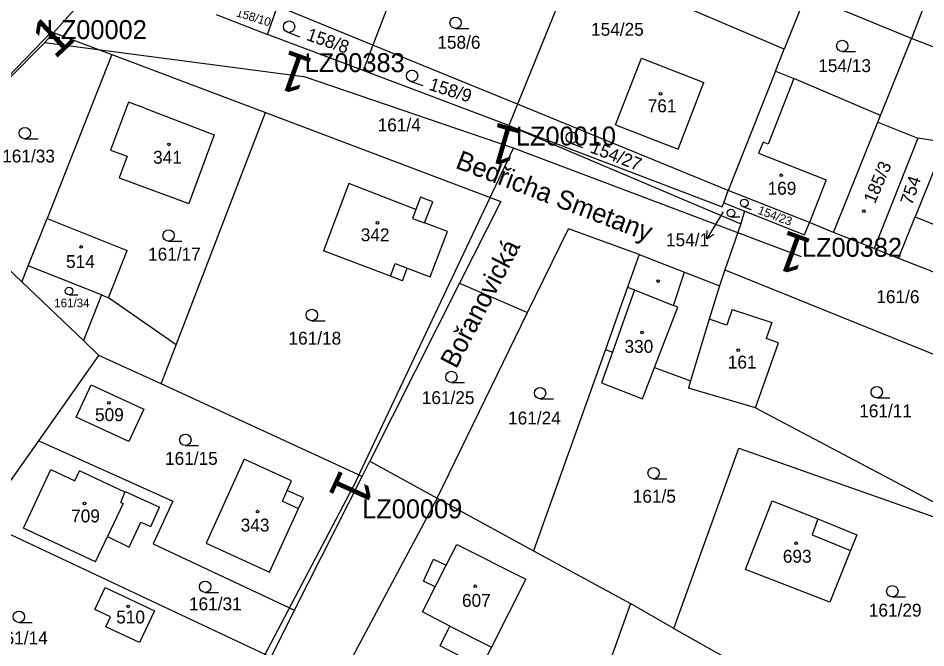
# Model space of a CAD drawing. Extents: x -738131 to -734179, y -1033447 to -1030078.
# Drawn here: x -736264.3 to -736144.6, y -1032442 to -1032359 of the extents above; entities that cross this region are included whole.
import ezdxf

# ---------------------------------------------------------------- set-up
doc = ezdxf.new("R2010")
doc.units = 0
for name, color, linetype in [('ftf_2050', 7, 'Continuous'), ('ftf_3010', 7, 'Continuous'), ('ftf_3010_ftf_3010_gtda_3015_gtda_3015_1', 7, 'Continuous'), ('ftf_nu', 7, 'Continuous'), ('Vrstva 1', 7, 'Continuous'), ('Vrstva 2', 7, 'Continuous'), ('Vrstva 3', 7, 'Continuous'), ('Vrstva 4', 7, 'Continuous'), ('Vrstva 5', 7, 'Continuous'), ('Vrstva 7', 7, 'Continuous')]:
    doc.layers.add(name, color=color, linetype=linetype)

msp = doc.modelspace()

# ---------------------------------------------------------------- linework, layer by layer
at = {"layer": 'ftf_2050'}
for points in [[(-736260.81, -1032362.16), (-736232.21, -1032330.19)], [(-736292.03, -1032393.62), (-736260.81, -1032362.16)], [(-736260.81, -1032362.16), (-736226.71, -1032366.65), (-736226.67, -1032366.68)], [(-736161.03, -1032390.44), (-736199.03, -1032376.09), (-736226.71, -1032366.65)], [(-736219.74, -1032419.93), (-736199.03, -1032376.09)], [(-736219.74, -1032419.93), (-736241.42, -1032461.24), (-736253.37, -1032482.1), (-736241.42, -1032461.24)]]:
    msp.add_lwpolyline(points, dxfattribs=at)
at = {"layer": 'Vrstva 1'}
for points in [[(-736212.82, -1032350.14), (-736217.57, -1032362.52)], [(-736190.8, -1032351.31), (-736198.5, -1032370.32)], [(-736163.32, -1032363.06), (-736190.8, -1032351.31)], [(-736143.39, -1032353.46), (-736146.54, -1032361.62)], [(-736160.47, -1032355.87), (-736163.32, -1032363.06)], [(-736146.54, -1032361.62), (-736160.47, -1032355.87)], [(-736231.46, -1032361.12), (-736230.15, -1032357.38)], [(-736217.57, -1032362.52), (-736230.15, -1032357.38)], [(-736238.22, -1032358.49), (-736231.46, -1032361.12)], [(-736278.41, -1032379.91), (-736259.94, -1032360.75)], [(-736259.94, -1032360.75), (-736252, -1032363.75)], [(-736218.85, -1032365.86), (-736231.46, -1032361.12)], [(-736150.62, -1032371.79), (-736146.54, -1032361.62)], [(-736131.88, -1032367.31), (-736146.54, -1032361.62)], [(-736217.57, -1032362.52), (-736218.85, -1032365.86)], [(-736198.5, -1032370.32), (-736217.57, -1032362.52)], [(-736252, -1032363.75), (-736260.53, -1032385.38)], [(-736252, -1032363.75), (-736231.73, -1032371.42)], [(-736164.47, -1032365.97), (-736163.32, -1032363.06)], [(-736185.58, -1032373.04), (-736182.15, -1032364.23)], [(-736182.15, -1032364.23), (-736173.9, -1032367.43)], [(-736199.63, -1032373.1), (-736218.85, -1032365.86)], [(-736164.47, -1032365.97), (-736170.7, -1032381.68)], [(-736164.47, -1032365.97), (-736162.05, -1032366.92)], [(-736177.32, -1032376.23), (-736173.9, -1032367.43)], [(-736150.62, -1032371.79), (-736162.05, -1032366.92)], [(-736249.78, -1032370.03), (-736252.17, -1032376.36)], [(-736247.62, -1032370.85), (-736249.78, -1032370.03)], [(-736247.62, -1032370.85), (-736238.49, -1032374.33)], [(-736198.5, -1032370.32), (-736199.63, -1032373.1)], [(-736170.7, -1032381.68), (-736198.5, -1032370.32)], [(-736243.49, -1032402.06), (-736231.73, -1032371.42)], [(-736231.73, -1032371.42), (-736200.7, -1032383.16)], [(-736150.99, -1032372.7), (-736150.62, -1032371.79)], [(-736199.63, -1032373.1), (-736169.05, -1032386.08)], [(-736199.63, -1032373.1), (-736171.48, -1032383.84)], [(-736185.58, -1032373.04), (-736177.32, -1032376.23)], [(-736156.82, -1032387.24), (-736150.99, -1032372.7)], [(-736150.99, -1032372.7), (-736145.68, -1032374.79)], [(-736238.49, -1032374.33), (-736241.83, -1032383.4)], [(-736145.68, -1032374.79), (-736151.46, -1032389.34)], [(-736142.11, -1032375.35), (-736146.06, -1032385.19)], [(-736142.11, -1032375.35), (-736145.68, -1032374.79)], [(-736252.17, -1032376.36), (-736249.98, -1032377.16)], [(-736249.98, -1032377.16), (-736251.03, -1032380.02)], [(-736263.86, -1032393.75), (-736278.41, -1032379.91)], [(-736251.03, -1032380.02), (-736241.83, -1032383.4)], [(-736220.71, -1032380.77), (-736224.07, -1032389.64)], [(-736211.88, -1032384.2), (-736220.71, -1032380.77)], [(-736171.29, -1032383.32), (-736170.7, -1032381.68)], [(-736159.98, -1032385.92), (-736170.7, -1032381.68)], [(-736211.27, -1032382.57), (-736211.88, -1032384.2)], [(-736209.66, -1032383.18), (-736211.27, -1032382.57)], [(-736200.7, -1032383.16), (-736206.13, -1032393.94)], [(-736210.73, -1032385.98), (-736209.66, -1032383.18)], [(-736171.48, -1032383.84), (-736171.29, -1032383.32)], [(-736171.29, -1032383.32), (-736168.49, -1032384.43)], [(-736263.03, -1032391.64), (-736260.53, -1032385.38)], [(-736260.53, -1032385.38), (-736249.95, -1032389.61)], [(-736169.05, -1032386.08), (-736168.49, -1032384.43)], [(-736168.49, -1032384.43), (-736160.63, -1032387.55)], [(-736148.26, -1032390.6), (-736146.06, -1032385.19)], [(-736207.73, -1032387.12), (-736210.73, -1032385.98)], [(-736197.16, -1032397.79), (-736191.78, -1032386.74)], [(-736182.43, -1032390.13), (-736191.78, -1032386.74)], [(-736169.05, -1032386.08), (-736171.13, -1032392.17)], [(-736160.63, -1032387.55), (-736159.98, -1032385.92)], [(-736156.82, -1032387.24), (-736159.98, -1032385.92)], [(-736210, -1032393.08), (-736207.73, -1032387.12)], [(-736151.46, -1032389.34), (-736156.82, -1032387.24)], [(-736252.42, -1032395.84), (-736249.95, -1032389.61)], [(-736215.25, -1032393), (-736224.07, -1032389.64)], [(-736182.43, -1032390.13), (-736183.97, -1032394.45)], [(-736182.43, -1032390.13), (-736176.46, -1032392.46)], [(-736151.46, -1032389.34), (-736148.26, -1032390.6)], [(-736148.26, -1032390.6), (-736128.1, -1032398.51)], [(-736263.86, -1032393.75), (-736263.03, -1032391.64)], [(-736253.35, -1032395.47), (-736263.03, -1032391.64)], [(-736213.67, -1032393.6), (-736213.03, -1032391.93)], [(-736213.03, -1032391.93), (-736210, -1032393.08)], [(-736176.46, -1032392.46), (-736171.85, -1032394.26)], [(-736171.13, -1032392.17), (-736171.85, -1032394.26)], [(-736171.13, -1032392.17), (-736131.75, -1032408.06)], [(-736263.86, -1032393.75), (-736255.73, -1032401.49)], [(-736206.13, -1032393.94), (-736217.97, -1032417.42)], [(-736213.67, -1032393.6), (-736215.25, -1032393)], [(-736206.13, -1032393.94), (-736197.16, -1032397.79)], [(-736183.97, -1032394.45), (-736186.9, -1032402.66)], [(-736171.85, -1032394.26), (-736173.2, -1032398.69)], [(-736253.35, -1032395.47), (-736255.73, -1032401.49)], [(-736243.49, -1032402.06), (-736252.42, -1032395.84)], [(-736170.17, -1032397.41), (-736170.87, -1032399.48)], [(-736170.17, -1032397.41), (-736164.97, -1032399.13)], [(-736209.07, -1032422.28), (-736197.16, -1032397.79)], [(-736173.2, -1032398.69), (-736175.66, -1032406.8)], [(-736170.87, -1032399.48), (-736173.2, -1032398.69)], [(-736164.97, -1032399.13), (-736165.68, -1032401.24)], [(-736255.73, -1032401.49), (-736253.68, -1032403.44)], [(-736245.47, -1032407.22), (-736243.49, -1032402.06)], [(-736167.11, -1032410.36), (-736164.08, -1032401.78)], [(-736164.08, -1032401.78), (-736165.68, -1032401.24)], [(-736261.63, -1032414.7), (-736253.68, -1032403.44)], [(-736245.47, -1032407.22), (-736253.68, -1032403.44)], [(-736186.9, -1032402.66), (-736196.38, -1032429.21)], [(-736185.97, -1032403.01), (-736187.41, -1032407.05)], [(-736186.9, -1032402.66), (-736185.97, -1032403.01)], [(-736182.02, -1032409.16), (-736180.42, -1032405.05)], [(-736180.42, -1032405.05), (-736175.66, -1032406.8)], [(-736187.41, -1032407.05), (-736182.02, -1032409.16)], [(-736175.66, -1032406.8), (-736175.96, -1032407.77)], [(-736256.69, -1032411.59), (-736254.73, -1032407.34)], [(-736254.73, -1032407.34), (-736247.77, -1032410.55)], [(-736218.98, -1032419.42), (-736245.47, -1032407.22)], [(-736167.11, -1032410.36), (-736175.96, -1032407.77)], [(-736247.77, -1032410.55), (-736249.73, -1032414.8)], [(-736167.11, -1032410.36), (-736137.84, -1032425.83)], [(-736249.73, -1032414.8), (-736256.69, -1032411.59)], [(-736269.14, -1032425.33), (-736261.63, -1032414.7)], [(-736261.63, -1032414.7), (-736243.95, -1032422.67)], [(-736177.86, -1032439.46), (-736169.31, -1032415.67)], [(-736169.31, -1032415.67), (-736138.11, -1032426.67)], [(-736234.53, -1032417.15), (-736235.76, -1032419.85)], [(-736228.29, -1032419.99), (-736234.53, -1032417.15)], [(-736218.98, -1032419.42), (-736217.97, -1032417.42)], [(-736217.97, -1032417.42), (-736209.07, -1032422.28)], [(-736263.63, -1032426.24), (-736260.03, -1032418.52)], [(-736260.03, -1032418.52), (-736256.86, -1032420)], [(-736256.86, -1032420), (-736256.25, -1032418.69)], [(-736250.26, -1032421.5), (-736256.25, -1032418.69)], [(-736235.76, -1032419.85), (-736239.55, -1032428.2)], [(-736228.85, -1032421.28), (-736228.29, -1032419.99)], [(-736227.88, -1032437.06), (-736218.98, -1032419.42)], [(-736250.26, -1032421.5), (-736250.21, -1032421.39)], [(-736250.21, -1032421.39), (-736245.69, -1032423.47)], [(-736226.71, -1032422.26), (-736228.85, -1032421.28)], [(-736227.35, -1032423.66), (-736226.71, -1032422.26)], [(-736209.07, -1032422.28), (-736224.81, -1032451.78)], [(-736209.07, -1032422.28), (-736196.38, -1032429.21)], [(-736168.42, -1032431.68), (-736164.89, -1032422.64)], [(-736164.89, -1032422.64), (-736158.88, -1032424.99)], [(-736246.86, -1032426.03), (-736245.69, -1032423.47)], [(-736243.95, -1032422.67), (-736246.53, -1032428.3)], [(-736231.19, -1032432.03), (-736227.35, -1032423.66)], [(-736158.88, -1032424.99), (-736153.72, -1032427.11)], [(-736269.14, -1032425.33), (-736230.99, -1032443.24)], [(-736254.12, -1032430.68), (-736263.63, -1032426.24)], [(-736249.68, -1032428.73), (-736248.15, -1032425.45)], [(-736248.15, -1032425.45), (-736246.86, -1032426.03)], [(-736254.12, -1032430.68), (-736252.56, -1032427.36)], [(-736252.56, -1032427.36), (-736249.68, -1032428.73)], [(-736153.72, -1032427.11), (-736154.56, -1032429.17)], [(-736246.53, -1032428.3), (-736227.88, -1032437.06)], [(-736239.55, -1032428.2), (-736231.19, -1032432.03)], [(-736207.9, -1032431.14), (-736206.49, -1032428.4)], [(-736206.49, -1032428.4), (-736197.39, -1032432.97)], [(-736196.38, -1032429.21), (-736183.6, -1032436.18)], [(-736154.56, -1032429.17), (-736157.31, -1032436.02)], [(-736210.87, -1032433.24), (-736209.55, -1032430.35)], [(-736209.55, -1032430.35), (-736207.9, -1032431.14)], [(-736157.31, -1032436.02), (-736168.42, -1032431.68)], [(-736209.35, -1032434), (-736210.87, -1032433.24)], [(-736197.39, -1032432.97), (-736201.92, -1032441.96)], [(-736254.22, -1032436.96), (-736252.87, -1032434.07)], [(-736252.87, -1032434.07), (-736246.35, -1032437.13)], [(-736211, -1032437.3), (-736209.35, -1032434)], [(-736252.15, -1032437.93), (-736254.22, -1032436.96)], [(-736183.6, -1032436.18), (-736192.74, -1032461.81)], [(-736177.86, -1032439.46), (-736183.6, -1032436.18)], [(-736252.76, -1032439.24), (-736252.15, -1032437.93)], [(-736246.35, -1032437.13), (-736248.32, -1032441.32)], [(-736230.99, -1032443.24), (-736227.88, -1032437.06)], [(-736207.39, -1032439.15), (-736211, -1032437.3)], [(-736248.32, -1032441.32), (-736252.76, -1032439.24)], [(-736208.69, -1032441.76), (-736207.39, -1032439.15)], [(-736177.86, -1032439.46), (-736170.55, -1032443.63)], [(-736203.28, -1032444.56), (-736208.69, -1032441.76)], [(-736201.92, -1032441.96), (-736203.28, -1032444.56)]]:
    msp.add_lwpolyline(points, dxfattribs=at)
at = {"layer": 'Vrstva 3'}
for p, q in [((-736206.65, -1032360.31), (-736204.9, -1032360.31)), ((-736228.87, -1032360.78), (-736227.24, -1032361.4)), ((-736155.66, -1032363.37), (-736153.91, -1032363.37)), ((-736212.63, -1032367.27), (-736210.98, -1032367.84)), ((-736263.46, -1032374.87), (-736261.71, -1032374.87)), ((-736191.57, -1032375.42), (-736189.93, -1032376.02)), ((-736168.77, -1032383.81), (-736167.67, -1032384.22)), ((-736170.34, -1032385.17), (-736169.17, -1032385.17)), ((-736244.5, -1032388.38), (-736242.75, -1032388.38)), ((-736257.62, -1032395.46), (-736256.45, -1032395.46)), ((-736225.61, -1032398.87), (-736223.86, -1032398.87)), ((-736207.21, -1032407.04), (-736205.46, -1032407.04)), ((-736195.51, -1032409.17), (-736193.76, -1032409.17)), ((-736151.12, -1032409.05), (-736149.37, -1032409.05)), ((-736242.29, -1032415.34), (-736240.54, -1032415.34)), ((-736180.54, -1032419.72), (-736178.79, -1032419.72)), ((-736239.68, -1032434.72), (-736237.93, -1032434.72)), ((-736149.06, -1032435.32), (-736147.31, -1032435.32)), ((-736264.24, -1032438.68), (-736262.49, -1032438.68))]:
    msp.add_line(p, q, dxfattribs=at)
for centre, radius in [((-736206.65, -1032359.56), 0.75), ((-736228.61, -1032360.08), 0.75), ((-736155.66, -1032362.62), 0.75), ((-736212.39, -1032366.56), 0.75), ((-736263.46, -1032374.12), 0.75), ((-736191.32, -1032374.72), 0.75), ((-736168.59, -1032383.34), 0.503), ((-736170.34, -1032384.67), 0.503), ((-736244.5, -1032387.63), 0.75), ((-736257.62, -1032394.96), 0.503), ((-736225.61, -1032398.12), 0.75), ((-736207.21, -1032406.29), 0.75), ((-736195.51, -1032408.42), 0.75), ((-736151.12, -1032408.3), 0.75), ((-736242.29, -1032414.59), 0.75), ((-736180.54, -1032418.97), 0.75), ((-736239.68, -1032433.97), 0.75), ((-736149.06, -1032434.57), 0.75), ((-736264.24, -1032437.93), 0.75)]:
    msp.add_circle(centre, radius, dxfattribs=at)
at = {"layer": 'Vrstva 4'}
for points in [[(-736162.05, -1032366.92), (-736165.45, -1032375.56)], [(-736166.1, -1032375.3), (-736166.69, -1032376.79)], [(-736165.45, -1032375.56), (-736166.1, -1032375.3)], [(-736166.69, -1032376.79), (-736157.77, -1032380.3)], [(-736157.77, -1032380.3), (-736159.98, -1032385.92)], [(-736211.88, -1032384.2), (-736212.33, -1032385.37)], [(-736212.33, -1032385.37), (-736210.73, -1032385.98)], [(-736146.06, -1032385.19), (-736139.95, -1032387.64)], [(-736215.25, -1032393), (-736214.61, -1032391.33)], [(-736214.61, -1032391.33), (-736213.03, -1032391.93)], [(-736177.9, -1032396.88), (-736176.46, -1032392.46)], [(-736183.04, -1032394.82), (-736185.97, -1032403.01)], [(-736183.97, -1032394.45), (-736183.04, -1032394.82)], [(-736183.04, -1032394.82), (-736177.9, -1032396.88)], [(-736253.35, -1032395.47), (-736252.42, -1032395.84)], [(-736180.42, -1032405.05), (-736177.34, -1032397.1)], [(-736177.34, -1032397.1), (-736177.9, -1032396.88)], [(-736229.49, -1032422.69), (-736228.85, -1032421.28)], [(-736250.81, -1032422.86), (-736250.26, -1032421.5)], [(-736250.51, -1032422.97), (-736252.56, -1032427.36)], [(-736250.81, -1032422.86), (-736250.51, -1032422.97)], [(-736229.49, -1032422.69), (-736227.35, -1032423.66)], [(-736158.88, -1032424.99), (-736159.64, -1032427.14)], [(-736159.64, -1032427.14), (-736154.56, -1032429.17)], [(-736209.35, -1032434), (-736207.9, -1032431.14)], [(-736207.39, -1032439.15), (-736201.92, -1032441.96)]]:
    msp.add_lwpolyline(points, dxfattribs=at)
at = {"layer": 'Vrstva 5'}
for centre in [(-736179.63, -1032368.95), (-736244.45, -1032375.61), (-736163.7, -1032379.69), (-736152.8, -1032384.43), (-736216.97, -1032385.96), (-736256.04, -1032389.14), (-736179.95, -1032393.64), (-736182.07, -1032400.42), (-736169.37, -1032402.77), (-736252.36, -1032409.71), (-736255.6, -1032422.99), (-736232.76, -1032424.06), (-736161.73, -1032428.24), (-736204.05, -1032433.91), (-736249.84, -1032436.56)]:
    msp.add_circle(centre, 0.175, dxfattribs=at)
at = {"layer": 'Vrstva 7'}
for p, q in [((-736172, -1032385.5), (-736173.54, -1032388.08)), ((-736173.54, -1032388.08), (-736173.46, -1032386.96)), ((-736173.54, -1032388.08), (-736172.6, -1032387.47))]:
    msp.add_line(p, q, dxfattribs=at)
msp.add_lwpolyline([(-736171.43, -1032384.55), (-736172, -1032385.5)], dxfattribs=at)

# ---------------------------------------------------------------- texts
at = {"layer": 'ftf_3010'}
for rotation, p in [(43.2385, (-736259.51, -1032364.5)), (160.2626, (-736225.22, -1032364.42)), (163.8283, (-736197.68, -1032373.77)), (159.9849, (-736159.48, -1032388.22)), (245.4227, (-736221.84, -1032418.26))]:
    msp.add_text('1', height=5.2, rotation=rotation, dxfattribs=at).set_placement(p)
at = {"layer": 'ftf_3010_ftf_3010_gtda_3015_gtda_3015_1'}
for s, p in [('LZ00002', (-736260.57, -1032361.72)), ('LZ00383', (-736226.56, -1032366.08)), ('LZ00382', (-736160.98, -1032390.44))]:
    msp.add_text(s, height=2.5, dxfattribs=at).set_placement(p)
for s, p in [('LZ00010', (-736198.7, -1032375.76)), ('LZ00009', (-736218.97, -1032424.94))]:
    msp.add_text(s, height=2.5, rotation=0, dxfattribs=at).set_placement(p)
at = {"layer": 'ftf_nu'}
for s, rotation, p in [('Bedřicha Smetany', 339.0302, (-736206.8, -1032378.68)), ('Bořanovická', 62.4769, (-736206.57, -1032405.32))]:
    msp.add_text(s, height=2.5, rotation=rotation, dxfattribs=at).set_placement(p)
at = {"layer": 'Vrstva 2'}
for s, height, rotation, p in [('158/10', 1.14, 342.723, (-736235.67, -1032358.69)), ('158/8', 1.7, 340.8862, (-736226.44, -1032361.81)), ('158/9', 1.7, 342.397, (-736210.28, -1032368.39)), ('154/27', 1.7, 338.8629, (-736189.03, -1032376.63)), ('185/3', 1.7, 66.8598, (-736151.36, -1032383.55)), ('754', 1.7, 71.6289, (-736146.45, -1032383.73)), ('154/23', 1.14, 339.5091, (-736166.9, -1032384.74))]:
    msp.add_text(s, height=height, rotation=rotation, dxfattribs=at).set_placement(p)
for s, height, p in [('154/25', 1.7, (-736188.79, -1032361.28)), ('158/6', 1.7, (-736209.06, -1032362.99)), ('154/13', 1.7, (-736158.83, -1032366.07)), ('761', 1.7, (-736181.32, -1032371.38)), ('161/4', 1.7, (-736216.93, -1032373.89)), ('161/33', 1.7, (-736266.44, -1032378)), ('341', 1.7, (-736246.54, -1032378.16)), ('169', 1.7, (-736165.51, -1032382.25)), ('154/1', 0.1, (-736171.58, -1032384.55)), ('342', 1.7, (-736219.16, -1032388.39)), ('161/17', 1.7, (-736247.21, -1032390.94)), ('514', 1.7, (-736258.02, -1032391.92)), ('161/6', 1.7, (-736151.17, -1032396.55)), ('161/34', 1.14, (-736259.58, -1032397.1)), ('161/18', 1.7, (-736228.69, -1032402.03)), ('330', 1.7, (-736184.38, -1032403.11)), ('161', 1.7, (-736170.76, -1032405.18)), ('161/25', 1.7, (-736211.11, -1032409.87)), ('509', 1.7, (-736254.2, -1032412.12)), ('161/11', 1.7, (-736153.43, -1032411.62)), ('161/24', 1.7, (-736199.73, -1032412.56)), ('161/15', 1.7, (-736244.97, -1032417.89)), ('161/5', 1.7, (-736183.29, -1032422.88)), ('709', 1.7, (-736257.35, -1032425.48)), ('343', 1.7, (-736234.99, -1032426.68)), ('693', 1.7, (-736163.5, -1032430.8)), ('161/31', 1.7, (-736241.81, -1032437.08)), ('607', 1.7, (-736205.81, -1032436.62)), ('161/29', 1.7, (-736152.16, -1032437.91)), ('510', 1.7, (-736251.4, -1032438.81)), ('161/14', 1.7, (-736267.39, -1032441.57))]:
    msp.add_text(s, height=height, dxfattribs=at).set_placement(p)
at = {"layer": 'Vrstva 7'}
msp.add_text('154/1', height=1.7, dxfattribs=at).set_placement((-736178.91, -1032389.05))

doc.saveas('drawing.dxf')
